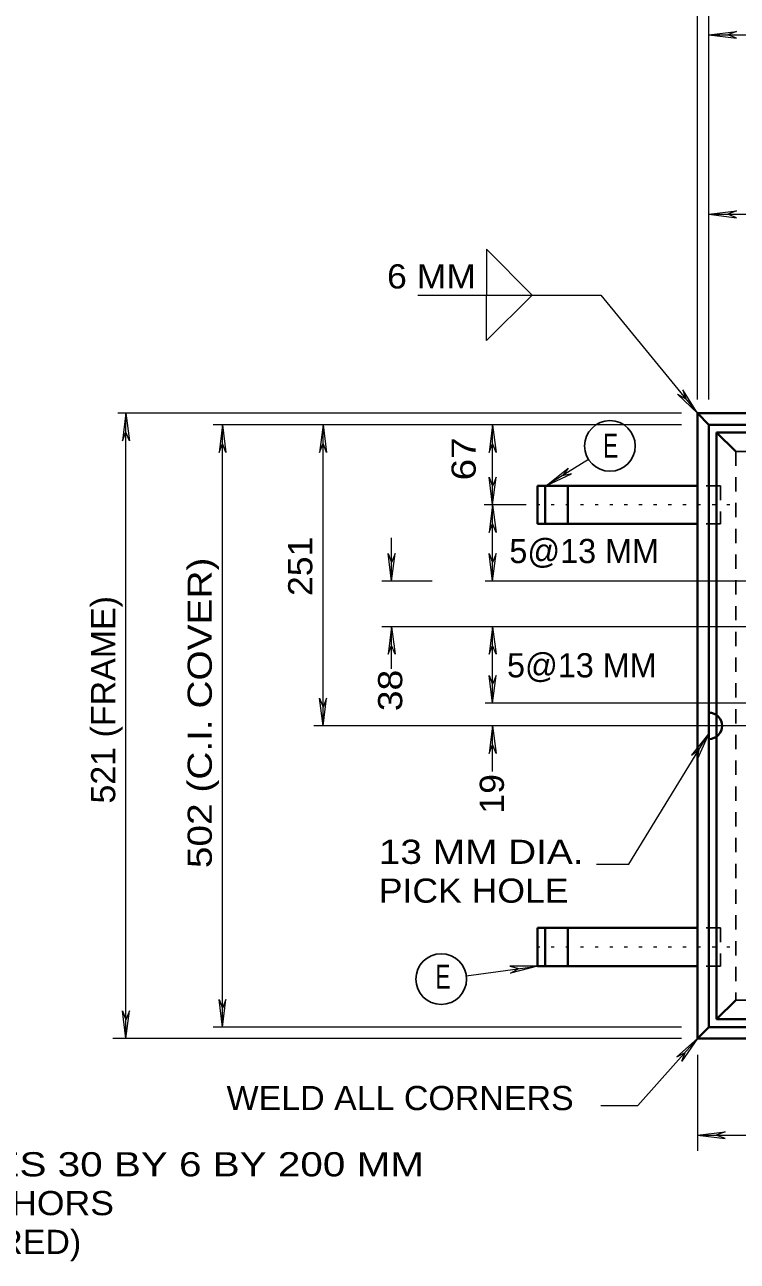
# Model space of a CAD drawing. Extents: x 312583 to 312854, y 144419 to 144597.
# Drawn here: x 312630.54 to 312652.93, y 144538.07 to 144576.94 of the extents above; entities that cross this region are included whole.
import ezdxf

# ---------------------------------------------------------------- set-up
doc = ezdxf.new("R2010")
doc.units = 0
doc.header["$LTSCALE"] = 0.3
doc.linetypes.add('DOTTED', pattern=[1.5, 0.3, -1.2])
doc.linetypes.add('SHORT_DASHED', pattern=[2.7, 1.5, -1.2])
doc.layers.add('1', color=7, linetype='Continuous', lineweight=13)

msp = doc.modelspace()

# ---------------------------------------------------------------- linework, layer by layer
at = {"layer": '1'}
for p, q in [((312651.6816, 144565.162), (312651.6816, 144581.3923)), ((312652.0419, 144565.162), (312652.0419, 144579.2456)), ((312652.0419, 144576.6236), (312652.9083, 144576.731)), ((312652.9083, 144576.731), (312652.6323, 144576.6236)), ((312652.0419, 144576.6236), (312670.1353, 144576.6236)), ((312652.0419, 144576.6236), (312652.9083, 144576.5163)), ((312652.9083, 144576.5163), (312652.6323, 144576.6236)), ((312652.0419, 144570.981), (312652.9083, 144571.0883)), ((312652.0419, 144570.981), (312654.5566, 144570.981)), ((312652.0419, 144570.981), (312652.9083, 144570.8736)), ((312652.9083, 144571.0883), (312652.6323, 144570.981)), ((312652.9083, 144570.8736), (312652.6323, 144570.981)), ((312642.8956, 144568.4433), (312648.6456, 144568.4433)), ((312648.6456, 144568.4433), (312651.6816, 144564.725)), ((312651.2216, 144565.461), (312651.3136, 144565.185)), ((312651.6816, 144564.725), (312651.2216, 144565.461)), ((312651.0529, 144565.3306), (312651.3136, 144565.185)), ((312651.6816, 144564.725), (312651.0529, 144565.3306)), ((312651.1756, 144564.725), (312633.4579, 144564.725)), ((312633.7186, 144564.725), (312633.6113, 144563.8586)), ((312633.7186, 144545.0753), (312633.7186, 144564.725)), ((312633.7186, 144564.725), (312633.8259, 144563.8586)), ((312651.1756, 144564.3646), (312636.4633, 144564.3646)), ((312636.7546, 144564.3646), (312636.6473, 144563.4983)), ((312636.7546, 144545.4356), (312636.7546, 144564.3646)), ((312636.7546, 144564.3646), (312636.8619, 144563.4983)), ((312639.9133, 144564.3646), (312639.8059, 144563.4983)), ((312639.9133, 144554.904), (312639.9133, 144564.3646)), ((312639.9133, 144564.3646), (312640.0206, 144563.4983)), ((312645.2416, 144564.3646), (312645.1343, 144563.4983)), ((312645.2416, 144561.85), (312645.2416, 144564.3646)), ((312645.2416, 144564.3646), (312645.3489, 144563.4983)), ((312633.6113, 144563.8586), (312633.7186, 144564.1346)), ((312633.8259, 144563.8586), (312633.7186, 144564.1346)), ((312636.6473, 144563.4983), (312636.7546, 144563.7743)), ((312636.8619, 144563.4983), (312636.7546, 144563.7743)), ((312639.8059, 144563.4983), (312639.9133, 144563.7743)), ((312640.0206, 144563.4983), (312639.9133, 144563.7743)), ((312645.1343, 144563.4983), (312645.2416, 144563.7743)), ((312645.3489, 144563.4983), (312645.2416, 144563.7743)), ((312648.2546, 144563.276), (312646.9359, 144562.4556)), ((312645.1343, 144562.7163), (312645.2416, 144562.4403)), ((312645.2416, 144561.85), (312645.1343, 144562.7163)), ((312645.3489, 144562.7163), (312645.2416, 144562.4403)), ((312645.2416, 144561.85), (312645.3489, 144562.7163)), ((312646.9359, 144562.4556), (312647.6183, 144563)), ((312646.9359, 144562.4556), (312647.7256, 144562.8236)), ((312647.6183, 144563), (312647.4343, 144562.7623)), ((312647.7256, 144562.8236), (312647.4343, 144562.7623)), ((312646.2996, 144561.85), (312644.9809, 144561.85)), ((312645.2416, 144561.85), (312645.1343, 144560.9836)), ((312645.2416, 144559.4503), (312645.2416, 144561.85)), ((312645.2416, 144561.85), (312645.3489, 144560.9836)), ((312645.1343, 144560.9836), (312645.2416, 144561.2596)), ((312645.3489, 144560.9836), (312645.2416, 144561.2596)), ((312642.0676, 144559.4503), (312642.0676, 144560.815)), ((312641.9603, 144560.3166), (312642.0676, 144560.0406)), ((312642.0676, 144559.4503), (312641.9603, 144560.3166)), ((312642.1749, 144560.3166), (312642.0676, 144560.0406)), ((312642.0676, 144559.4503), (312642.1749, 144560.3166)), ((312645.1343, 144560.3166), (312645.2416, 144560.0406)), ((312645.2416, 144559.4503), (312645.1343, 144560.3166)), ((312645.3489, 144560.3166), (312645.2416, 144560.0406)), ((312645.2416, 144559.4503), (312645.3489, 144560.3166)), ((312643.3403, 144559.4503), (312641.7609, 144559.4503)), ((312654.2423, 144559.4503), (312645.0116, 144559.4503)), ((312654.2423, 144558.0166), (312641.7609, 144558.0166)), ((312642.0676, 144558.0166), (312641.9603, 144557.1503)), ((312642.0676, 144556.698), (312642.0676, 144558.0166)), ((312642.0676, 144558.0166), (312642.1749, 144557.1503)), ((312645.2416, 144558.0166), (312645.1343, 144557.1503)), ((312645.2416, 144555.617), (312645.2416, 144558.0166)), ((312645.2416, 144558.0166), (312645.3489, 144557.1503)), ((312641.9603, 144557.1503), (312642.0676, 144557.4263)), ((312642.1749, 144557.1503), (312642.0676, 144557.4263)), ((312645.1343, 144557.1503), (312645.2416, 144557.4263)), ((312645.3489, 144557.1503), (312645.2416, 144557.4263)), ((312645.1343, 144556.4833), (312645.2416, 144556.2073)), ((312645.2416, 144555.617), (312645.1343, 144556.4833)), ((312645.3489, 144556.4833), (312645.2416, 144556.2073)), ((312645.2416, 144555.617), (312645.3489, 144556.4833)), ((312639.8059, 144555.7703), (312639.9133, 144555.4943)), ((312639.9133, 144554.904), (312639.8059, 144555.7703)), ((312640.0206, 144555.7703), (312639.9133, 144555.4943)), ((312639.9133, 144554.904), (312640.0206, 144555.7703)), ((312654.2423, 144555.617), (312645.0116, 144555.617)), ((312656.1436, 144554.904), (312639.6219, 144554.904)), ((312645.2416, 144554.904), (312645.1343, 144554.0376)), ((312645.2416, 144553.4703), (312645.2416, 144554.904)), ((312645.2416, 144554.904), (312645.3489, 144554.0376)), ((312652.0419, 144554.6586), (312651.4976, 144553.9763)), ((312652.0419, 144554.6586), (312651.6816, 144553.869)), ((312645.1343, 144554.0376), (312645.2416, 144554.3136)), ((312645.3489, 144554.0376), (312645.2416, 144554.3136)), ((312651.4976, 144553.9763), (312651.7353, 144554.1603)), ((312651.6816, 144553.869), (312651.7353, 144554.1603)), ((312644.4136, 144547.0456), (312646.6523, 144547.3523)), ((312646.6523, 144547.3523), (312645.7783, 144547.3446)), ((312645.7783, 144547.3446), (312646.0696, 144547.2756)), ((312646.6523, 144547.3523), (312645.8089, 144547.13)), ((312645.8089, 144547.13), (312646.0696, 144547.2756)), ((312636.6473, 144546.302), (312636.7546, 144546.026)), ((312636.7546, 144545.4356), (312636.6473, 144546.302)), ((312636.8619, 144546.302), (312636.7546, 144546.026)), ((312636.7546, 144545.4356), (312636.8619, 144546.302)), ((312633.6113, 144545.9416), (312633.7186, 144545.6656)), ((312633.7186, 144545.0753), (312633.6113, 144545.9416)), ((312633.8259, 144545.9416), (312633.7186, 144545.6656)), ((312633.7186, 144545.0753), (312633.8259, 144545.9416)), ((312651.1756, 144545.4356), (312636.4633, 144545.4356)), ((312651.1756, 144545.0753), (312633.3046, 144545.0753)), ((312651.6816, 144545.0753), (312651.0299, 144544.5003)), ((312651.6816, 144545.0753), (312651.1909, 144544.3623)), ((312651.0299, 144544.5003), (312651.2906, 144544.6383)), ((312651.1909, 144544.3623), (312651.2906, 144544.6383)), ((312651.6816, 144544.5616), (312651.6816, 144541.5486)), ((312651.6816, 144542.0393), (312652.5479, 144542.1466)), ((312652.5479, 144542.1466), (312652.2719, 144542.0393)), ((312651.6816, 144542.0393), (312657.6769, 144542.0393)), ((312651.6816, 144542.0393), (312652.5479, 144541.932)), ((312652.5479, 144541.932), (312652.2719, 144542.0393))]:
    msp.add_line(p, q, dxfattribs=at)
at = {"layer": '1', "lineweight": 40}
for p, q in [((312651.6816, 144564.725), (312688.5813, 144564.725)), ((312651.6816, 144564.725), (312651.6816, 144545.0753)), ((312651.6816, 144564.725), (312652.0419, 144564.3646)), ((312652.0419, 144564.3646), (312652.0419, 144545.4356)), ((312652.0419, 144564.3646), (312688.2209, 144564.3646)), ((312652.2796, 144564.127), (312652.2796, 144545.681)), ((312652.2796, 144564.127), (312687.9833, 144564.127)), ((312652.2796, 144564.127), (312652.8853, 144563.529)), ((312646.6523, 144562.448), (312646.6523, 144561.252)), ((312651.6816, 144562.448), (312646.6523, 144562.448)), ((312646.8899, 144562.448), (312646.8899, 144561.252)), ((312647.6106, 144562.448), (312647.6106, 144561.252)), ((312651.6816, 144561.252), (312646.6523, 144561.252)), ((312646.6523, 144548.556), (312646.6523, 144547.3523)), ((312651.6816, 144548.556), (312646.6523, 144548.556)), ((312646.8899, 144548.556), (312646.8899, 144547.3523)), ((312647.6106, 144548.556), (312647.6106, 144547.3523)), ((312651.6816, 144547.3523), (312646.6523, 144547.3523)), ((312652.2796, 144545.681), (312652.8853, 144546.279)), ((312652.2796, 144545.681), (312687.9833, 144545.681)), ((312651.6816, 144545.0753), (312652.0419, 144545.4356)), ((312652.0419, 144545.4356), (312688.2209, 144545.4356)), ((312651.6816, 144545.0753), (312688.5813, 144545.0753))]:
    msp.add_line(p, q, dxfattribs=at)
at = {"layer": '1', "linetype": 'SHORT_DASHED', "lineweight": 25}
for p, q in [((312652.8853, 144563.529), (312687.3853, 144563.529)), ((312652.8853, 144563.529), (312652.8853, 144546.279)), ((312652.4023, 144562.448), (312651.6816, 144562.448)), ((312652.4023, 144562.448), (312652.4023, 144561.252)), ((312652.4023, 144561.252), (312651.6816, 144561.252)), ((312652.4023, 144548.556), (312651.6816, 144548.556)), ((312652.4023, 144548.556), (312652.4023, 144547.3523)), ((312652.4023, 144547.3523), (312651.6816, 144547.3523)), ((312652.8853, 144546.279), (312687.3853, 144546.279))]:
    msp.add_line(p, q, dxfattribs=at)
at = {"layer": '1', "linetype": 'DOTTED'}
for p, q in [((312652.7013, 144561.85), (312646.2996, 144561.85)), ((312652.7013, 144547.9503), (312646.2996, 144547.9503))]:
    msp.add_line(p, q, dxfattribs=at)
at = {"layer": '1'}
for points in [[(312646.4836, 144568.4433), (312645.0499, 144569.8846), (312645.0499, 144568.4433)], [(312646.4836, 144568.4433), (312645.0499, 144567.0096), (312645.0499, 144568.4433)], [(312648.5076, 144550.557), (312649.5273, 144550.557), (312652.0419, 144554.6586)], [(312648.6456, 144542.967), (312649.8033, 144542.967), (312651.6816, 144545.0753)]]:
    msp.add_lwpolyline(points, dxfattribs=at)
at = {"layer": '1', "lineweight": 25}
for centre in [(312648.9293, 144563.6996), (312643.6259, 144546.9421)]:
    msp.add_circle(centre, 0.7964, dxfattribs=at)
at = {"layer": '1', "lineweight": 40}
msp.add_arc((312652.0429, 144554.9021), 0.414, 270, 90, dxfattribs=at)

# ---------------------------------------------------------------- texts
at = {"layer": '1'}
for s, width, p in [('6 MM', 1.1, (312641.924, 144568.6494)), ('E', 0.7, (312648.7155, 144563.3277)), ('13 MM DIA.', 1.2, (312641.6639, 144550.5636)), ('PICK HOLE', 1.1, (312641.6639, 144549.3436)), ('E', 0.7, (312643.4457, 144546.6393)), ('WELD ALL CORNERS', 1.05, (312636.8796, 144542.8241)), ('DENOTES 30 BY 6 BY 200 MM', 1.25, (312625.0783, 144540.7426)), ('STL. ANCHORS', 1.1, (312625.0783, 144539.5226)), ('(8 REQUIRED)', 1.05, (312625.0783, 144538.3026))]:
    msp.add_text(s, height=0.76, dxfattribs=dict(at, width=width)).set_placement(p)
for s, width, p in [('67 ', 1.2, (312644.7106, 144562.6165)), ('251 ', 1.1, (312639.5755, 144558.983)), ('502 (C.I. COVER)', 1.2, (312636.4168, 144550.4309)), ('521 (FRAME)', 1.05, (312633.3807, 144552.46)), ('38 ', 1.15, (312642.4013, 144555.3641)), ('19 ', 1.1, (312645.5974, 144552.1442))]:
    msp.add_text(s, height=0.76, rotation=90, dxfattribs=dict(at, width=width)).set_placement(p)
for p in [(312645.7681, 144560.0177), (312645.6945, 144556.4258)]:
    msp.add_text('5@13 MM', height=0.76, dxfattribs=at).set_placement(p)

doc.saveas('drawing.dxf')
